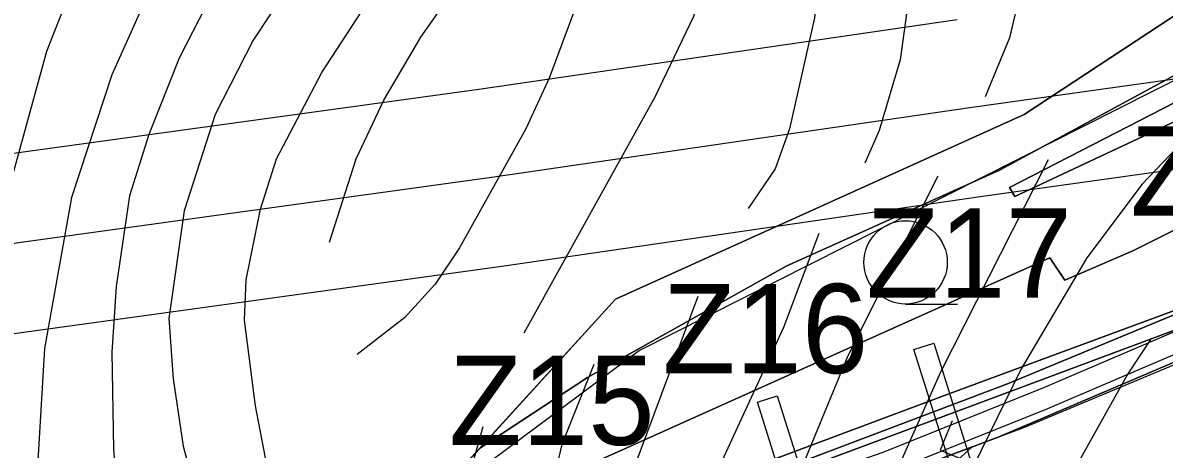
# Model space of a CAD drawing. Extents: x -1900516 to -575031, y -3809306 to -1157387.
# Drawn here: x -577522.2 to -577330.4, y -1158028.7 to -1157957 of the extents above; entities that cross this region are included whole.
import ezdxf

# ---------------------------------------------------------------- set-up
doc = ezdxf.new("R2010")
doc.units = 0
for name, color, linetype in [('01_OBVOD PÚ', 7, 'Continuous'), ('01_PARCELY_NÁVRH_PC', 7, 'Continuous'), ('01_PARCELY_NÁVRH_ŽP', 7, 'Continuous'), ('01_SPRÁV_HRANICE', 7, 'Continuous'), ('01_VRSTEVNICE', 7, 'Continuous'), ('02_KULTURY STAV', 7, 'Continuous'), ('03_PC_NÁVRH', 7, 'Continuous'), ('03_PC_OBJEKTY_NÁVRH', 7, 'Continuous'), ('04_ZPF_OP_ORGAN', 7, 'Continuous'), ('06_ÚSES_IP', 7, 'Continuous'), ('07_ELEKTRO', 7, 'Continuous'), ('07_OCH_P A POPISY TI', 7, 'Continuous')]:
    doc.layers.add(name, color=color, linetype=linetype)

msp = doc.modelspace()

# ---------------------------------------------------------------- linework, layer by layer
at = {"layer": '01_OBVOD PÚ'}
msp.add_lwpolyline([(-577534.09, -1158094.32), (-577489.61, -1158071.28), (-577453.7, -1158037.24), (-577451.36, -1158035.02), (-577422.63, -1158003.44), (-577353.97, -1157972.45), (-577295.57, -1157933.94), (-577285.23, -1157927.12), (-577272.66, -1157918.83), (-577267.57, -1157912.7), (-577264.59, -1157908.83), (-577259.68, -1157904.15), (-577235.52, -1157888.94), (-577208.15, -1157858.38), (-577141.24, -1157808.38)], dxfattribs=at)
at = {"layer": '01_PARCELY_NÁVRH_PC'}
for points in [[(-577168.2, -1157836.45), (-577206.33, -1157869.32), (-577211.99, -1157876.61), (-577214.63, -1157884.54), (-577215.14, -1157889.32), (-577215.62, -1157924.63), (-577215.79, -1157937.28), (-577215.81, -1157939.06), (-577217.7, -1157945.8), (-577223.11, -1157955.25), (-577233.03, -1157964.72), (-577235.52, -1157967.09), (-577245.89, -1157971.76), (-577293.94, -1157991.65), (-577356.76, -1158017.67), (-577431.65, -1158046.04), (-577444.45, -1158052.55), (-577452.88, -1158057.98), (-577461.16, -1158059.8), (-577462.96, -1158060.67), (-577478.1, -1158070.42), (-577483.65, -1158076.66), (-577540.89, -1158110.96)], [(-577530.93, -1158114.23), (-577496.81, -1158093.48), (-577445.49, -1158062.41), (-577428.41, -1158053.47), (-577410.05, -1158046.2), (-577391.45, -1158039.19), (-577378.68, -1158034.31), (-577362.71, -1158028.28), (-577353.76, -1158024.93), (-577298.39, -1158001.8)], [(-577422.07, -1158221.62), (-577405.29, -1158166.63), (-577401.81, -1158140.64), (-577395.98, -1158089.98), (-577391.03, -1158073.38), (-577387.56, -1158067.74), (-577382.06, -1158058.65), (-577380.79, -1158056.24), (-577377.12, -1158048.62), (-577370.93, -1158035.79), (-577362.71, -1158028.28), (-577378.68, -1158034.31), (-577375.69, -1158037.57), (-577380.28, -1158047.1), (-577383.91, -1158054.66), (-577385.11, -1158056.92), (-577390.55, -1158065.92), (-577394.25, -1158071.94), (-577399.42, -1158089.27), (-577405.28, -1158140.21), (-577408.72, -1158165.88), (-577425.58, -1158221.16)]]:
    msp.add_lwpolyline(points, dxfattribs=at)
at = {"layer": '01_PARCELY_NÁVRH_ŽP'}
for points in [[(-577295.57, -1157933.94), (-577353.97, -1157972.45), (-577388.3, -1157987.94), (-577422.63, -1158003.44), (-577451.36, -1158035.02), (-577471.66, -1158054.26), (-577489.61, -1158071.28), (-577511.85, -1158082.8), (-577534.09, -1158094.32)], [(-577540.89, -1158110.96), (-577483.65, -1158076.66), (-577478.1, -1158070.42), (-577462.96, -1158060.67), (-577461.16, -1158059.8), (-577452.88, -1158057.98), (-577444.45, -1158052.55), (-577431.65, -1158046.04), (-577356.76, -1158017.67), (-577293.94, -1157991.65)]]:
    msp.add_lwpolyline(points, dxfattribs=at)
at = {"layer": '01_SPRÁV_HRANICE'}
for p, q in [((-577353.97, -1157972.45), (-577295.57, -1157933.94)), ((-577422.63, -1158003.44), (-577353.97, -1157972.45)), ((-577451.36, -1158035.02), (-577422.63, -1158003.44))]:
    msp.add_line(p, q, dxfattribs=at)
at = {"layer": '01_VRSTEVNICE'}
for points in [[(-577529.31, -1157767.73), (-577528.85, -1157768.26), (-577512.21, -1157784.76), (-577482.86, -1157812.14), (-577426.7, -1157860.25), (-577410.62, -1157877.74), (-577402.58, -1157888.61), (-577397.5, -1157896.93), (-577393.83, -1157904.83), (-577389.45, -1157920.64), (-577388.04, -1157928.54), (-577387.48, -1157940.39), (-577389.17, -1157956.19), (-577393.41, -1157974.82), (-577395.8, -1157981.59), (-577400.32, -1157988.22)], [(-577437.99, -1158009.1), (-577415.98, -1157969.45), (-577409.49, -1157955.91), (-577407.23, -1157949.14), (-577404.83, -1157933.33), (-577404.97, -1157919.79), (-577407.8, -1157903.99), (-577413.58, -1157890.44), (-577422.75, -1157876.9), (-577430.94, -1157866.46), (-577454.5, -1157842.33), (-577469.6, -1157828.5), (-577484.41, -1157816.65), (-577502.47, -1157800.99), (-577511.64, -1157792.38), (-577517.57, -1157788.15), (-577535.57, -1157772.12)], [(-577542.05, -1157776.66), (-577527.73, -1157789), (-577492.45, -1157816.23), (-577481.31, -1157825.68), (-577457.6, -1157848.26), (-577450.27, -1157856.16), (-577436.58, -1157872.95), (-577429.53, -1157885.65), (-577426.28, -1157894.11), (-577424.31, -1157902.58), (-577422.75, -1157915.27), (-577422.75, -1157923.74), (-577423.6, -1157932.21), (-577427.41, -1157949.14), (-577433.76, -1157966.35), (-577437.71, -1157974.82), (-577448.85, -1157994.85), (-577452.95, -1158000.92), (-577458.03, -1158006.56), (-577466.07, -1158012.77)], [(-577470.72, -1157993.86), (-577466.21, -1157979.9), (-577461.55, -1157970.02), (-577455.34, -1157959.44), (-577445.75, -1157945.75), (-577440.39, -1157935.59), (-577438.56, -1157930.51), (-577436.16, -1157916.97), (-577436.3, -1157903.14), (-577438.98, -1157891.29), (-577442.51, -1157881.41), (-577446.6, -1157873.51), (-577449.84, -1157868.85), (-577461.69, -1157855.87), (-577487.51, -1157831.04), (-577493.86, -1157824.13), (-577548.65, -1157781.29)], [(-577479.19, -1158049.74), (-577479.9, -1158038.31), (-577483.14, -1158021.38), (-577484.97, -1158006.99), (-577484.69, -1158000.21), (-577482.29, -1157988.36), (-577479.61, -1157979.9), (-577471.99, -1157965.36), (-577455.91, -1157940.67), (-577451.25, -1157930.79), (-577449.42, -1157925.15), (-577447.58, -1157914.99), (-577447.58, -1157914.57), (-577448.01, -1157905.4), (-577449.42, -1157896.65), (-577452.52, -1157886.49), (-577455.2, -1157881.41), (-577466.63, -1157863.92), (-577484.41, -1157842.33), (-577514.6, -1157814.25), (-577536.76, -1157797.32), (-577552.72, -1157784.14)], [(-577557.36, -1157787.39), (-577533.51, -1157807.48), (-577499.79, -1157838.94), (-577487.8, -1157852.91), (-577475.1, -1157871.54), (-577468.04, -1157883.39), (-577464.38, -1157891.29), (-577461.98, -1157899.19), (-577460.71, -1157909.07), (-577461.27, -1157916.97), (-577463.1, -1157924.87), (-577468.19, -1157936.72), (-577483.53, -1157959.96), (-577489.91, -1157972.42), (-577495.13, -1157988.64), (-577497.67, -1158006.7), (-577496.97, -1158016.86), (-577495.27, -1158028.15), (-577490.76, -1158045.08), (-577490.46, -1158057.61)], [(-577561.98, -1157790.63), (-577555.8, -1157795.91), (-577519.4, -1157829.49), (-577502.19, -1157848.11), (-577492.88, -1157859.54), (-577481.31, -1157876.61), (-577475.1, -1157890.16), (-577473.55, -1157895.24), (-577471.99, -1157905.4), (-577472.28, -1157913.86), (-577473.97, -1157920.92), (-577477.36, -1157929.38), (-577486.95, -1157945.33), (-577495.98, -1157962.96), (-577501.06, -1157975.8), (-577504.3, -1157986.1), (-577506.56, -1158001.34), (-577507.27, -1158012.35), (-577506.98, -1158028.71), (-577505.15, -1158049.88), (-577505.29, -1158058.34), (-577506.56, -1158068.36)], [(-577568.4, -1157795.13), (-577547.34, -1157813.69), (-577528.29, -1157831.75), (-577501.34, -1157863.92), (-577494.43, -1157874.64), (-577486.81, -1157890.72), (-577483.99, -1157901.45), (-577483.85, -1157912.17), (-577486.95, -1157922.89), (-577492.88, -1157933.62), (-577507.27, -1157965.79), (-577514.04, -1157986.39), (-577518.56, -1158011.78), (-577520.11, -1158037.18), (-577519.97, -1158058.34), (-577521.52, -1158079.08)], [(-577573.48, -1157798.69), (-577555.8, -1157813.97), (-577537.74, -1157832.74), (-577523.63, -1157849.24), (-577515.03, -1157861.09), (-577510.23, -1157869), (-577502.75, -1157884.8), (-577500.64, -1157892.7), (-577499.51, -1157906.53), (-577501.91, -1157920.21), (-577518.27, -1157961.83), (-577526.6, -1157992.03), (-577528.99, -1158005.57), (-577533.37, -1158041.13), (-577535.06, -1158064.83), (-577538.17, -1158081.76), (-577540.99, -1158090.94)], [(-577463.1, -1157820.74), (-577425.72, -1157851.64), (-577414.71, -1157861.52), (-577406.1, -1157870.55), (-577396.37, -1157882.26), (-577386.07, -1157896.23), (-577380.71, -1157906.53), (-577375.91, -1157918.38), (-577373.79, -1157926.28), (-577372.52, -1157936.16), (-577372.67, -1157947.73), (-577374.78, -1157963.25), (-577378.31, -1157975.1), (-577380.71, -1157980.6)], [(-577427.13, -1157840.78), (-577394.11, -1157870.12), (-577374.64, -1157890.72), (-577369.28, -1157897.78), (-577363.49, -1157907.66), (-577359.83, -1157915.56), (-577356.72, -1157925.43), (-577354.18, -1157937.57), (-577354.6, -1157951.68), (-577356.44, -1157959.58), (-577360.53, -1157969.45)], [(-577319.05, -1157968.32), (-577334.15, -1157984.13), (-577343.46, -1157996.54), (-577354.46, -1158015.17), (-577366.6, -1158040), (-577378.03, -1158067.94), (-577385.36, -1158089.67), (-577393.27, -1158117.6), (-577396.65, -1158134.53), (-577398.63, -1158161.62), (-577400.74, -1158209.03)], [(-577349.95, -1157980.04), (-577368.01, -1158015.73), (-577383.11, -1158049.59), (-577393.97, -1158080.07), (-577401.45, -1158105.47), (-577405.12, -1158127.48), (-577408.5, -1158159.65), (-577409.91, -1158185.04)], [(-577420.92, -1158174.6), (-577412.31, -1158100.95), (-577409.21, -1158086.28), (-577401.59, -1158060.6), (-577394.11, -1158038.59), (-577383.53, -1158012.91), (-577368.43, -1157982.72)], [(-577388.47, -1157992.45), (-577394.39, -1158008.25), (-577411.18, -1158044.52), (-577417.96, -1158068.22), (-577419.79, -1158078.38), (-577422.75, -1158110.55), (-577432, -1158165.7), (-577436.44, -1158193.51)], [(-577388.47, -1157992.45), (-577394.39, -1158008.25), (-577411.18, -1158044.52), (-577417.96, -1158068.22), (-577419.79, -1158078.38), (-577422.75, -1158110.55), (-577432, -1158165.7), (-577436.44, -1158193.51)], [(-577388.47, -1157992.45), (-577394.39, -1158008.25), (-577411.18, -1158044.52), (-577417.96, -1158068.22), (-577419.79, -1158078.38), (-577422.75, -1158110.55), (-577432, -1158165.7), (-577436.44, -1158193.51)], [(-577408.81, -1158003), (-577427.13, -1158052.13), (-577430.51, -1158069.91), (-577435.73, -1158120.99), (-577441.09, -1158152.59), (-577454.78, -1158219.75), (-577461.41, -1158245.43), (-577470.58, -1158265.18), (-577488.78, -1158294.25), (-577496.26, -1158308.64), (-577503.46, -1158327.27), (-577507.69, -1158344.2), (-577509.38, -1158354.35), (-577510.94, -1158374.67), (-577510.94, -1158397.25), (-577509.38, -1158413.05), (-577504.3, -1158440.7), (-577500.78, -1158464.41), (-577500.92, -1158480.21), (-577501.91, -1158486.14), (-577506.98, -1158504.34), (-577504.33, -1158514.25), (-577518.13, -1158524.79), (-577531.68, -1158537.49)], [(-577332.74, -1158010.23), (-577336.55, -1158016.02), (-577357.99, -1158054.39), (-577364.91, -1158070.19), (-577373.37, -1158092.77), (-577379.01, -1158113.09), (-577385.65, -1158142.15), (-577388.33, -1158162.47), (-577389.74, -1158268.57)], [(-577426.28, -1158014.46), (-577431.64, -1158027.87), (-577439.26, -1158060.03), (-577443.49, -1158100.11), (-577461.13, -1158194.64), (-577464.23, -1158208.47), (-577471.15, -1158228.22), (-577478.63, -1158244.02), (-577509.24, -1158291.43), (-577516.58, -1158305.25), (-577523.49, -1158323.03)], [(-577444.91, -1158024.9), (-577447.87, -1158035.49), (-577450.83, -1158056.65), (-577457.6, -1158126.91), (-577465.22, -1158164.16), (-577477.92, -1158204.8), (-577487.94, -1158228.5), (-577493.44, -1158238.66), (-577507.55, -1158258.69), (-577525.47, -1158280.14)]]:
    msp.add_lwpolyline(points, dxfattribs=at)
at = {"layer": '02_KULTURY STAV'}
for points in [[(-577445.44, -1158028.52), (-577422.63, -1158003.44), (-577353.97, -1157972.45), (-577295.57, -1157933.94), (-577285.23, -1157927.12), (-577272.66, -1157918.83), (-577267.57, -1157912.7), (-577264.59, -1157908.83), (-577259.68, -1157904.15), (-577240.59, -1157892.13), (-577243.76, -1157898.94), (-577253.46, -1157906.95), (-577264.66, -1157909.16), (-577267.17, -1157912.52), (-577267.91, -1157917.11), (-577267.76, -1157922.58), (-577265.98, -1157924.16), (-577290.1, -1157947.24), (-577306.04, -1157953.55), (-577358.1, -1157981.81), (-577393.96, -1157997.93), (-577427.34, -1158016.62)], [(-577356.43, -1157984.71), (-577310.77, -1157961.25), (-577287.11, -1157947.71), (-577261.07, -1157928.53), (-577259.14, -1157930.24), (-577284.87, -1157948.41), (-577321.23, -1157970.13), (-577355.56, -1157986.23)], [(-577464.58, -1158062.52), (-577448.39, -1158048.04), (-577446.57, -1158040.04), (-577349.63, -1157996.53), (-577347.14, -1158000.26), (-577335.68, -1157995.36), (-577312.02, -1157983.45), (-577278.39, -1157964.52), (-577262.2, -1157954.25), (-577245.39, -1157942.47), (-577239.19, -1157947.98), (-577234.72, -1157952.43), (-577233.17, -1157955.42), (-577234.09, -1157958.65), (-577256.43, -1157969.58), (-577271.21, -1157979.3), (-577284.77, -1157986.5), (-577295.25, -1157991.72), (-577324.15, -1158003.68), (-577366.03, -1158019.16), (-577404.66, -1158033.61), (-577439.57, -1158048.33)]]:
    msp.add_lwpolyline(points, close=True, dxfattribs=at)
for points in [[(-577312.02, -1157983.45), (-577335.68, -1157995.36), (-577347.14, -1158000.26), (-577349.63, -1157996.53), (-577446.57, -1158040.04), (-577445.9, -1158037.06), (-577446.52, -1158035.55), (-577448.18, -1158031.53), (-577445.44, -1158028.52), (-577427.34, -1158016.62), (-577393.96, -1157997.93), (-577358.1, -1157981.81), (-577306.04, -1157953.55)], [(-577540.7, -1158112.86), (-577505.19, -1158092.47), (-577469.52, -1158070.31), (-577451.56, -1158058.71), (-577438.32, -1158051.44), (-577403.42, -1158036.52), (-577365.15, -1158022.26), (-577322.54, -1158006.4), (-577294.78, -1157994.84), (-577283.67, -1157989.47), (-577269.8, -1157982.03), (-577254.77, -1157972.54), (-577241.59, -1157966.17), (-577227.3, -1157959.59), (-577221.99, -1157962.98), (-577214.07, -1157983.93), (-577209.14, -1158064.94), (-577208.59, -1158168), (-577200.48, -1158214.38)], [(-577310.77, -1157961.25), (-577356.43, -1157984.71), (-577355.56, -1157986.23), (-577321.23, -1157970.13)], [(-577542.12, -1158110.27), (-577506.87, -1158089.89), (-577470.93, -1158067.74), (-577464.58, -1158062.52), (-577439.57, -1158048.33), (-577404.66, -1158033.61), (-577366.03, -1158019.16), (-577324.15, -1158003.68)], [(-577542.12, -1158110.27), (-577506.87, -1158089.89), (-577470.93, -1158067.74), (-577464.58, -1158062.52), (-577439.57, -1158048.33), (-577404.66, -1158033.61), (-577366.03, -1158019.16), (-577324.15, -1158003.68)], [(-577373.89, -1158004.28), (-577365.14, -1158004.28)], [(-577322.54, -1158006.4), (-577365.15, -1158022.26), (-577403.42, -1158036.52), (-577438.32, -1158051.44), (-577451.56, -1158058.71), (-577469.52, -1158070.31), (-577505.19, -1158092.47), (-577540.7, -1158112.86)], [(-577322.54, -1158006.4), (-577365.15, -1158022.26), (-577403.42, -1158036.52), (-577438.32, -1158051.44), (-577451.56, -1158058.71), (-577469.52, -1158070.31), (-577505.19, -1158092.47), (-577540.7, -1158112.86)]]:
    msp.add_lwpolyline(points, dxfattribs=at)
msp.add_circle((-577373.89, -1157997.28), 7, dxfattribs=at)
at = {"layer": '03_PC_NÁVRH'}
msp.add_lwpolyline([(-577526.11, -1158106.17), (-577515.12, -1158099.98), (-577494.04, -1158087.25), (-577471.9, -1158072.74), (-577448.97, -1158056.45), (-577445.36, -1158054.35), (-577435.32, -1158050.06), (-577425.28, -1158045.77), (-577401.48, -1158037.48), (-577377.67, -1158029.19), (-577350.65, -1158018.32), (-577304.33, -1157998.49), (-577252.54, -1157978.57), (-577228.61, -1157966.73), (-577214.21, -1157946.69), (-577212, -1157883.57), (-577204.66, -1157871.59), (-577155.57, -1157831.3), (-577059.67, -1157775.49), (-576980.41, -1157741.06), (-576924.81, -1157699.32), (-576866.49, -1157631.93)], dxfattribs=at)
at = {"layer": '03_PC_OBJEKTY_NÁVRH'}
for points in [[(-577594.09, -1158162.2), (-577573.25, -1158144.13), (-577562.16, -1158134.47), (-577548.23, -1158123.83), (-577534.85, -1158115.12), (-577491.59, -1158089.24), (-577454.34, -1158065.95), (-577442.73, -1158059.46), (-577423.84, -1158049.97), (-577377.39, -1158032.8), (-577350.01, -1158021.83), (-577304.55, -1158002.4), (-577271.7, -1157989.26), (-577230.69, -1157971.26), (-577216.81, -1157958.88)], [(-577372.49, -1158011.93), (-577369.15, -1158010.88), (-577362.86, -1158030.92), (-577366.2, -1158031.97), (-577372.49, -1158011.93)], [(-577398.78, -1158020.78), (-577395.45, -1158019.73), (-577389.16, -1158039.76), (-577392.49, -1158040.81), (-577398.78, -1158020.78)], [(-577366.05, -1158023.93), (-577368.06, -1158028.83), (-577363.16, -1158030.85)]]:
    msp.add_lwpolyline(points, dxfattribs=at)
at = {"layer": '04_ZPF_OP_ORGAN'}
for points in [[(-577548.67, -1158122.54), (-577513.86, -1158102.14), (-577492.71, -1158089.36), (-577472.01, -1158075.87), (-577471.06, -1158077.31), (-577447.01, -1158060.25), (-577443.83, -1158058.38), (-577424.06, -1158050.25), (-577386.8, -1158037.35), (-577358.35, -1158026.66), (-577319.32, -1158010.04), (-577226.17, -1157966.64), (-577222.41, -1158009.02), (-577217.54, -1158062.91), (-577208.59, -1158168), (-577200.48, -1158214.38)], [(-577200.48, -1158214.38), (-577208.59, -1158168), (-577217.54, -1158062.91), (-577222.41, -1158009.02), (-577226.17, -1157966.64), (-577319.32, -1158010.04), (-577358.35, -1158026.66), (-577386.8, -1158037.35), (-577424.06, -1158050.25), (-577443.83, -1158058.38), (-577447.01, -1158060.25), (-577471.06, -1158077.31), (-577472.01, -1158075.87), (-577492.71, -1158089.36), (-577513.86, -1158102.14), (-577548.67, -1158122.54)]]:
    msp.add_lwpolyline(points, dxfattribs=at)
at = {"layer": '06_ÚSES_IP'}
msp.add_lwpolyline([(-577271.75, -1157928.78), (-577297.88, -1157951.09), (-577418.59, -1158012.1), (-577451.04, -1158036.22), (-577459.88, -1158052.18), (-577548.64, -1158110.02), (-577615.62, -1158164.89), (-577684.57, -1158225.77)], dxfattribs=at)
at = {"layer": '07_ELEKTRO'}
msp.add_lwpolyline([(-576613.64, -1157879.01), (-576701.48, -1157891.16), (-576783, -1157902.14), (-576868.21, -1157913.92), (-576958.94, -1157926.41), (-577060.41, -1157940.16), (-577166.82, -1157954.4), (-577258.94, -1157956.97), (-577319.09, -1157965.17), (-577363.1, -1157971.3), (-577443.48, -1157983.02), (-577522.09, -1157993.86), (-577610.84, -1158006.39), (-577703.33, -1158019.18), (-577796.56, -1158031.66)], dxfattribs=at)
at = {"layer": '07_OCH_P A POPISY TI'}
for p, q in [((-577445.59, -1157968.17), (-577365.22, -1157956.45)), ((-577524.16, -1157979), (-577445.59, -1157968.17)), ((-577360.98, -1157986.15), (-577317.04, -1157980.03)), ((-577441.37, -1157997.87), (-577360.98, -1157986.15)), ((-577520.02, -1158008.72), (-577441.37, -1157997.87)), ((-577608.78, -1158021.25), (-577520.02, -1158008.72))]:
    msp.add_line(p, q, dxfattribs=at)

# ---------------------------------------------------------------- texts
at = {"layer": '03_PC_OBJEKTY_NÁVRH'}
for s, p in [('Z18', (-577336.12, -1157989.43)), ('Z17', (-577380.49, -1158003.2)), ('Z16', (-577414.72, -1158015.9)), ('Z15', (-577450.62, -1158027.95))]:
    msp.add_text(s, height=15, dxfattribs=at).set_placement(p)

doc.saveas('drawing.dxf')
